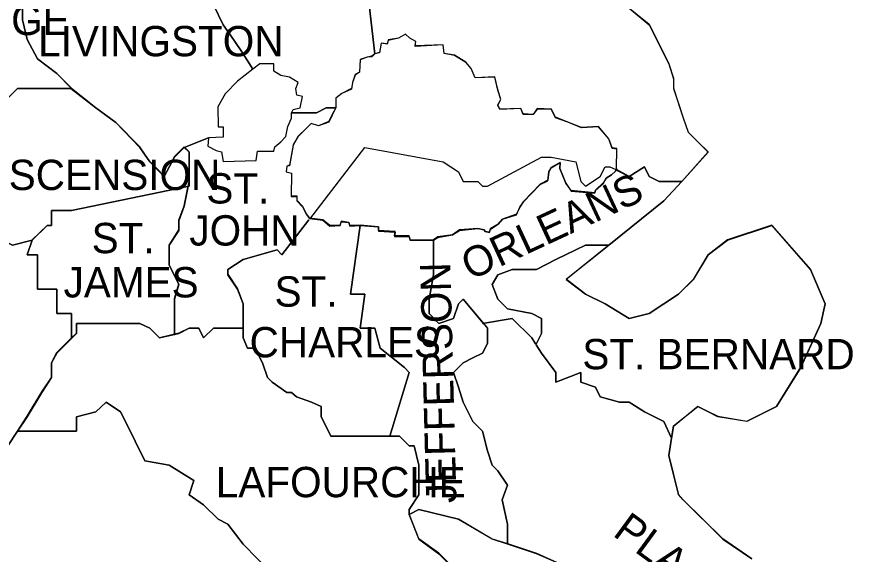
# Model space of a CAD drawing. Extents: x 0.19 to 2.82, y 0.04 to 1.79.
# Drawn here: x 2.4368 to 2.5672, y 1.4495 to 1.5325 of the extents above; entities that cross this region are included whole.
import ezdxf

# ---------------------------------------------------------------- set-up
doc = ezdxf.new("R2010")
doc.units = 0
for name, color, linetype in [('Dist02', 7, 'Continuous'), ('Dist61', 7, 'Continuous'), ('Dist62', 7, 'Continuous'), ('Standard Info', 7, 'Continuous')]:
    doc.layers.add(name, color=color, linetype=linetype)

msp = doc.modelspace()

# ---------------------------------------------------------------- linework, layer by layer
at = {"layer": 'Dist02'}
for points in [[(2.5294, 1.50908), (2.52924, 1.50867), (2.52865, 1.50808), (2.52782, 1.50758), (2.5274, 1.50692), (2.52615, 1.50575), (2.52607, 1.50533), (2.5224, 1.50567), (2.52157, 1.50683), (2.52065, 1.50908), (2.52074, 1.51), (2.51932, 1.50925), (2.51899, 1.50858), (2.51882, 1.50725), (2.51765, 1.50667), (2.51507, 1.504), (2.51449, 1.50308), (2.51399, 1.502), (2.51182, 1.50125), (2.51115, 1.5005), (2.5099, 1.49975), (2.50982, 1.49925), (2.50915, 1.49933), (2.50899, 1.49958), (2.50799, 1.49983), (2.50515, 1.49958), (2.50407, 1.49883), (2.50182, 1.4985), (2.50115, 1.49808)], [(2.53949, 1.50708), (2.53599, 1.50708), (2.53449, 1.50783), (2.53374, 1.50933), (2.5314, 1.50783), (2.5294, 1.50892)], [(2.53674, 1.50408), (2.53949, 1.50708)], [(2.52824, 1.49725), (2.53674, 1.50408)], [(2.4819, 1.50117), (2.47774, 1.49575), (2.47699, 1.4965), (2.47174, 1.495), (2.4694, 1.4935), (2.4694, 1.49275), (2.4709, 1.4905), (2.47174, 1.48817), (2.47174, 1.48442)], [(2.48982, 1.50033), (2.48824, 1.50025), (2.48807, 1.50075), (2.4869, 1.50092), (2.48674, 1.50033), (2.48515, 1.50025), (2.48407, 1.50117), (2.48199, 1.50142)], [(2.50115, 1.49808), (2.49757, 1.498), (2.4974, 1.49867), (2.49515, 1.49867), (2.49524, 1.49933), (2.49265, 1.4995), (2.49265, 1.50008), (2.48982, 1.50033)], [(2.5379, 1.4675), (2.53824, 1.46933), (2.54199, 1.47233), (2.54507, 1.47083), (2.54957, 1.47008), (2.55415, 1.47233), (2.5579, 1.47842), (2.56099, 1.48517), (2.56165, 1.48817), (2.5594, 1.4935), (2.5534, 1.50033), (2.54657, 1.49808), (2.54357, 1.49575), (2.54132, 1.492), (2.53899, 1.48967), (2.53449, 1.48667), (2.5314, 1.48592), (2.52765, 1.48817), (2.52465, 1.48967), (2.52165, 1.492), (2.52824, 1.49725)], [(2.47174, 1.48442), (2.46715, 1.48442), (2.46565, 1.48292), (2.4649, 1.48442), (2.4634, 1.48442), (2.46182, 1.48367), (2.45882, 1.48292), (2.45732, 1.48442), (2.45582, 1.48517), (2.45357, 1.48517), (2.44599, 1.48517), (2.44599, 1.48367), (2.44299, 1.48067), (2.44215, 1.47908), (2.44215, 1.47683), (2.44065, 1.47458), (2.4384, 1.47083), (2.4369, 1.4685)], [(2.4369, 1.4685), (2.4354, 1.46625), (2.43315, 1.4625), (2.43007, 1.461), (2.42932, 1.46025), (2.42707, 1.45875), (2.42482, 1.45942), (2.42332, 1.45875), (2.42182, 1.45725), (2.41874, 1.45417), (2.41724, 1.45192), (2.41799, 1.44967), (2.41799, 1.44817), (2.42032, 1.44508), (2.42182, 1.44358), (2.42182, 1.44208), (2.42099, 1.44133), (2.41949, 1.43983), (2.41799, 1.43825), (2.41574, 1.43492)], [(2.55032, 1.44883), (2.54582, 1.45192), (2.53974, 1.45792), (2.53899, 1.45875), (2.53749, 1.46475), (2.5379, 1.46742)], [(2.48407, 1.43608), (2.48532, 1.43525), (2.48907, 1.43075), (2.49207, 1.42617), (2.49665, 1.42092), (2.49815, 1.41942), (2.50115, 1.42092), (2.50424, 1.42317), (2.50799, 1.427), (2.50874, 1.42917), (2.50799, 1.43), (2.50799, 1.43375), (2.51024, 1.43825), (2.50874, 1.44283), (2.50499, 1.44658), (2.50199, 1.44967), (2.4989, 1.45192), (2.4974, 1.45567)], [(2.4974, 1.45567), (2.4989, 1.45642), (2.50499, 1.45492), (2.51024, 1.45192), (2.51257, 1.45117)], [(2.51257, 1.45117), (2.51707, 1.44967), (2.52232, 1.44733)]]:
    msp.add_lwpolyline(points, dxfattribs=at)
at = {"layer": 'Dist61'}
for points in [[(2.44524, 1.5215), (2.44299, 1.52375), (2.43999, 1.526), (2.4384, 1.529), (2.43765, 1.53208), (2.43765, 1.53508), (2.43765, 1.53892), (2.4384, 1.54117), (2.43999, 1.54417), (2.44215, 1.54642), (2.44374, 1.54867), (2.44524, 1.55017), (2.44674, 1.55325)], [(2.4634, 1.50633), (2.4634, 1.51167), (2.46265, 1.51242), (2.46115, 1.51092), (2.45957, 1.50783), (2.45882, 1.50867), (2.45732, 1.51017), (2.45582, 1.51242), (2.45207, 1.51617), (2.44899, 1.51842), (2.44515, 1.5215)], [(2.46115, 1.48367), (2.46115, 1.48667), (2.46115, 1.489), (2.46182, 1.49125), (2.46032, 1.49425), (2.46032, 1.49575), (2.46032, 1.49725), (2.46182, 1.49958), (2.46182, 1.50108), (2.46265, 1.50333), (2.46324, 1.50642)], [(2.44524, 1.48292), (2.44599, 1.48367), (2.44599, 1.48517), (2.45357, 1.48517), (2.45582, 1.48517), (2.45732, 1.48442), (2.45882, 1.48292), (2.46115, 1.4835)], [(2.4309, 1.46133), (2.43315, 1.4625), (2.4354, 1.46625), (2.4369, 1.4685), (2.4384, 1.47083), (2.44065, 1.47458), (2.44215, 1.47683), (2.44215, 1.47908), (2.44299, 1.48067), (2.44524, 1.48292)]]:
    msp.add_lwpolyline(points, dxfattribs=at)
at = {"layer": 'Dist62'}
for points in [[(2.44524, 1.5215), (2.44299, 1.52375), (2.43999, 1.526), (2.4384, 1.529), (2.43765, 1.53208), (2.43765, 1.53508), (2.43765, 1.53892), (2.4384, 1.54117), (2.43999, 1.54417), (2.44215, 1.54642), (2.44374, 1.54867), (2.44524, 1.55017), (2.44674, 1.55325)], [(2.52174, 1.551), (2.52232, 1.548), (2.5239, 1.54492), (2.52765, 1.53808), (2.53074, 1.53433), (2.53449, 1.53133), (2.53749, 1.52525), (2.53824, 1.523), (2.53824, 1.5215), (2.53974, 1.51692), (2.54049, 1.51467), (2.54199, 1.51317), (2.54357, 1.51167), (2.53949, 1.50708)], [(2.5294, 1.50908), (2.52949, 1.51217), (2.52874, 1.51225), (2.52824, 1.51367), (2.52665, 1.51558), (2.52399, 1.51542), (2.5219, 1.51625), (2.51999, 1.517), (2.5194, 1.51825), (2.51715, 1.51833), (2.51657, 1.51742), (2.51499, 1.5175), (2.51465, 1.51833), (2.5114, 1.51825), (2.51107, 1.51892), (2.51157, 1.51975), (2.51107, 1.52125), (2.51065, 1.52325), (2.50757, 1.52308), (2.50699, 1.5245), (2.50615, 1.5255), (2.5044, 1.52658), (2.50282, 1.52683), (2.50265, 1.52817), (2.49832, 1.528), (2.4984, 1.52867), (2.49749, 1.52917), (2.49682, 1.52983), (2.49574, 1.52917), (2.49415, 1.52892), (2.49399, 1.52833), (2.49307, 1.52842), (2.49282, 1.527), (2.49207, 1.52675)], [(2.49207, 1.52675), (2.49165, 1.52642), (2.4909, 1.52625), (2.48982, 1.52592), (2.48974, 1.52392), (2.48907, 1.52358), (2.48865, 1.52233), (2.48849, 1.52142), (2.48699, 1.52067), (2.48607, 1.51992), (2.48607, 1.51842)], [(2.4634, 1.50633), (2.4634, 1.51167), (2.46265, 1.51242), (2.46115, 1.51092), (2.45957, 1.50783), (2.45882, 1.50867), (2.45732, 1.51017), (2.45582, 1.51242), (2.45207, 1.51617), (2.44899, 1.51842), (2.44515, 1.5215)], [(2.48607, 1.51842), (2.48549, 1.51742), (2.48499, 1.51633), (2.4834, 1.51567), (2.48224, 1.516), (2.48149, 1.51525), (2.48024, 1.51408), (2.47949, 1.51275), (2.4789, 1.50958), (2.47849, 1.50942), (2.4784, 1.50858), (2.47924, 1.50833), (2.47915, 1.50483), (2.48007, 1.50483), (2.48007, 1.50417), (2.4809, 1.50325), (2.48149, 1.50208), (2.48199, 1.50142)], [(2.53949, 1.50708), (2.53599, 1.50708), (2.53449, 1.50783), (2.53374, 1.50933), (2.5314, 1.50783), (2.5294, 1.50892)], [(2.46115, 1.48367), (2.46115, 1.48667), (2.46115, 1.489), (2.46182, 1.49125), (2.46032, 1.49425), (2.46032, 1.49575), (2.46032, 1.49725), (2.46182, 1.49958), (2.46182, 1.50108), (2.46265, 1.50333), (2.46324, 1.50642)], [(2.4819, 1.50117), (2.47774, 1.49575), (2.47699, 1.4965), (2.47174, 1.495), (2.4694, 1.4935), (2.4694, 1.49275), (2.4709, 1.4905), (2.47174, 1.48817), (2.47174, 1.48442)], [(2.47174, 1.48442), (2.46715, 1.48442), (2.46565, 1.48292), (2.4649, 1.48442), (2.4634, 1.48442), (2.46182, 1.48367), (2.46115, 1.4835)]]:
    msp.add_lwpolyline(points, dxfattribs=at)
at = {"layer": 'Standard Info'}
for p, q in [((2.4664, 1.51383), (2.46265, 1.51233)), ((2.46265, 1.51233), (2.4664, 1.51383)), ((2.46265, 1.51233), (2.4664, 1.51383)), ((2.50882, 1.48517), (2.50874, 1.48517)), ((2.46115, 1.48358), (2.46115, 1.48342)), ((2.51699, 1.48183), (2.51707, 1.48208)), ((2.4369, 1.4685), (2.4369, 1.4685))]:
    msp.add_line(p, q, dxfattribs=at)
for points in [[(2.48307, 1.58192), (2.48149, 1.57283), (2.48457, 1.57058), (2.48532, 1.56833), (2.48607, 1.56458), (2.48757, 1.5615), (2.48832, 1.56), (2.48832, 1.55925), (2.48982, 1.5555), (2.48982, 1.54642), (2.49207, 1.52675)], [(2.47324, 1.52442), (2.47324, 1.52442), (2.47174, 1.52675), (2.47024, 1.529), (2.46865, 1.53125), (2.46715, 1.53433), (2.4679, 1.55625), (2.4679, 1.56075), (2.46715, 1.58117)], [(2.44674, 1.55317), (2.44524, 1.55017), (2.44374, 1.54867), (2.44215, 1.54642), (2.43999, 1.54408), (2.4384, 1.54108), (2.43765, 1.53883), (2.43765, 1.535), (2.43765, 1.532), (2.4384, 1.529), (2.43999, 1.526), (2.44299, 1.52375), (2.44524, 1.52142)], [(2.49207, 1.52675), (2.48982, 1.54642), (2.48982, 1.554)], [(2.52174, 1.551), (2.52232, 1.54792), (2.5239, 1.54492), (2.52765, 1.53808), (2.53074, 1.53433), (2.53449, 1.53125), (2.53749, 1.52525), (2.53824, 1.52292), (2.53824, 1.52142), (2.53974, 1.51692), (2.54049, 1.51467), (2.54199, 1.51317), (2.54357, 1.51158), (2.53949, 1.50708)], [(2.46765, 1.54842), (2.46715, 1.53433), (2.46865, 1.53125), (2.47024, 1.529), (2.47174, 1.52675), (2.47324, 1.52442)], [(2.46265, 1.51233), (2.46115, 1.51083), (2.45957, 1.50783), (2.45882, 1.50858), (2.45732, 1.51008), (2.45582, 1.51233), (2.45207, 1.51617), (2.44899, 1.51842), (2.44524, 1.52142), (2.44299, 1.52375), (2.43999, 1.526), (2.4384, 1.529), (2.43765, 1.532), (2.43765, 1.535), (2.43765, 1.53883), (2.4384, 1.54108), (2.43999, 1.54408), (2.44215, 1.54642), (2.44274, 1.54725)], [(2.5294, 1.509), (2.52949, 1.51208), (2.52874, 1.51217), (2.52824, 1.51367), (2.52665, 1.5155), (2.52399, 1.51533), (2.5219, 1.51625), (2.51999, 1.51692), (2.5194, 1.51817), (2.51715, 1.51825), (2.51657, 1.51742), (2.51499, 1.51742), (2.51465, 1.51833), (2.5114, 1.51817), (2.51107, 1.51883), (2.51157, 1.51975), (2.51107, 1.52117), (2.51065, 1.52317), (2.50757, 1.52308), (2.50699, 1.5245), (2.50615, 1.52542), (2.5044, 1.5265), (2.50282, 1.52683), (2.50265, 1.52817), (2.49832, 1.52792), (2.4984, 1.52867), (2.49749, 1.52917), (2.49682, 1.52983), (2.49574, 1.52917), (2.49415, 1.52883), (2.49399, 1.52825), (2.49307, 1.52842), (2.49282, 1.52692), (2.49207, 1.52675)], [(2.49207, 1.52675), (2.49165, 1.52633), (2.4909, 1.52625), (2.48982, 1.52583), (2.48974, 1.52392), (2.48907, 1.5235), (2.48865, 1.52233), (2.48849, 1.52133), (2.48699, 1.52067), (2.48607, 1.51992), (2.48607, 1.51842)], [(2.47324, 1.52442), (2.4709, 1.52258), (2.46899, 1.52058), (2.46782, 1.51858), (2.4679, 1.5155), (2.46865, 1.5155), (2.46865, 1.51392), (2.4664, 1.51383), (2.46265, 1.51233)], [(2.47924, 1.51767), (2.47949, 1.51817), (2.48057, 1.51842), (2.4809, 1.52017), (2.48007, 1.52042), (2.4799, 1.52142), (2.48024, 1.52233), (2.4789, 1.52317), (2.47757, 1.52342), (2.47649, 1.52408), (2.47649, 1.52525), (2.47432, 1.52525), (2.47324, 1.52442)], [(2.42857, 1.49725), (2.42857, 1.4995), (2.42857, 1.501), (2.43007, 1.50258), (2.43007, 1.50408), (2.4309, 1.50558), (2.43157, 1.51158), (2.4339, 1.51842), (2.4369, 1.52142), (2.44524, 1.52142)], [(2.44524, 1.52142), (2.4369, 1.52142), (2.43465, 1.51917)], [(2.44515, 1.52142), (2.44899, 1.51842), (2.45207, 1.51617), (2.45582, 1.51233), (2.45732, 1.51008), (2.45882, 1.50858), (2.45957, 1.50783), (2.46115, 1.51083), (2.46265, 1.51233), (2.4634, 1.51158), (2.4634, 1.50633)], [(2.48607, 1.51842), (2.48549, 1.51733), (2.48499, 1.51625), (2.4834, 1.51567), (2.48224, 1.516), (2.48149, 1.51525), (2.48024, 1.514), (2.47949, 1.51267), (2.4789, 1.5095), (2.47849, 1.50942), (2.4784, 1.50858), (2.47924, 1.50833), (2.47915, 1.50475), (2.48007, 1.50475), (2.48007, 1.50408), (2.4809, 1.50317), (2.48149, 1.502), (2.48199, 1.50133)], [(2.48607, 1.51842), (2.48457, 1.51842), (2.48307, 1.51767), (2.47924, 1.51767)], [(2.47924, 1.51767), (2.48307, 1.51767), (2.48457, 1.51842), (2.48607, 1.51842)], [(2.4664, 1.51383), (2.46632, 1.5125), (2.46757, 1.51183), (2.4684, 1.51167), (2.46865, 1.51017), (2.47374, 1.51033), (2.47399, 1.51175), (2.47649, 1.51175), (2.47665, 1.51242), (2.47757, 1.51317), (2.47832, 1.514), (2.47865, 1.51558), (2.47924, 1.51683), (2.47924, 1.51767)], [(2.46115, 1.48358), (2.46115, 1.48667), (2.46115, 1.48892), (2.46182, 1.49117), (2.46032, 1.49417), (2.46032, 1.49575), (2.46032, 1.49725), (2.46182, 1.4995), (2.46182, 1.501), (2.46265, 1.50325), (2.4634, 1.50708), (2.4634, 1.51158), (2.46265, 1.51233)], [(2.48207, 1.50125), (2.49057, 1.51233), (2.50265, 1.51008), (2.50499, 1.50858), (2.50574, 1.50708), (2.50799, 1.50708), (2.50874, 1.50633), (2.50949, 1.50633), (2.51782, 1.51083), (2.51932, 1.51083), (2.52315, 1.51008), (2.5239, 1.50708), (2.52465, 1.50633), (2.5269, 1.50783), (2.52765, 1.50933), (2.5284, 1.50933), (2.52932, 1.50892)], [(2.48207, 1.50125), (2.49057, 1.51233), (2.50265, 1.51008), (2.50499, 1.50858), (2.50574, 1.50708), (2.50799, 1.50708), (2.50874, 1.50633), (2.50949, 1.50633), (2.51782, 1.51083), (2.51932, 1.51083), (2.52315, 1.51008), (2.5239, 1.50708), (2.52465, 1.50633), (2.5269, 1.50783), (2.52765, 1.50933), (2.5284, 1.50933), (2.52932, 1.50892)], [(2.50115, 1.498), (2.50182, 1.49842), (2.50407, 1.49883), (2.50515, 1.4995), (2.50799, 1.49983), (2.50899, 1.49958), (2.50915, 1.49933), (2.50982, 1.49917), (2.5099, 1.49967), (2.51115, 1.5005), (2.51182, 1.50125), (2.51399, 1.50192), (2.51449, 1.50308), (2.51507, 1.50392), (2.51765, 1.50658), (2.51882, 1.50717), (2.51899, 1.50858), (2.51932, 1.50917), (2.52074, 1.51), (2.52065, 1.50908), (2.52157, 1.50683), (2.5224, 1.50558), (2.52607, 1.50525), (2.52615, 1.50575), (2.5274, 1.50683), (2.52782, 1.50758), (2.52865, 1.50808), (2.52924, 1.50867), (2.5294, 1.509)], [(2.5294, 1.50883), (2.5314, 1.50783), (2.53374, 1.50933), (2.53449, 1.50783), (2.53599, 1.50708), (2.53949, 1.50708)], [(2.53899, 1.50708), (2.53599, 1.50708), (2.53449, 1.50783), (2.53374, 1.50933), (2.5314, 1.50783), (2.5294, 1.50883)], [(2.4634, 1.50633), (2.44524, 1.50258), (2.44215, 1.50258), (2.44215, 1.50025), (2.44149, 1.50025), (2.43915, 1.498), (2.43615, 1.49725), (2.43465, 1.498), (2.4339, 1.498), (2.4324, 1.498), (2.4309, 1.498), (2.43007, 1.49875), (2.42857, 1.49725)], [(2.43915, 1.49808), (2.44149, 1.50025), (2.44215, 1.50025), (2.44215, 1.50258), (2.44524, 1.50258), (2.4634, 1.50633)], [(2.46324, 1.50633), (2.46265, 1.50325), (2.46182, 1.501), (2.46182, 1.4995), (2.46032, 1.49725), (2.46032, 1.49575), (2.46032, 1.49417), (2.46182, 1.49117), (2.46115, 1.48892), (2.46115, 1.48667), (2.46115, 1.48358)], [(2.53949, 1.50708), (2.53674, 1.50408)], [(2.53674, 1.50408), (2.52824, 1.49725)], [(2.4819, 1.50117), (2.47774, 1.49575), (2.47699, 1.4965), (2.47174, 1.495), (2.4694, 1.4935), (2.4694, 1.49267), (2.4709, 1.49042), (2.47174, 1.48817), (2.47174, 1.48442)], [(2.47174, 1.48442), (2.47174, 1.48817), (2.4709, 1.49042), (2.4694, 1.49267), (2.4694, 1.4935), (2.47174, 1.495), (2.47699, 1.4965), (2.47774, 1.49575), (2.4819, 1.50117)], [(2.48199, 1.50133), (2.48407, 1.50108), (2.48515, 1.50017), (2.48674, 1.50025), (2.4869, 1.50083), (2.48807, 1.50075), (2.48824, 1.50017), (2.48982, 1.50025)], [(2.48982, 1.50025), (2.48832, 1.48967), (2.49057, 1.48967), (2.48982, 1.48442), (2.49207, 1.48442), (2.4929, 1.48133), (2.49665, 1.47833), (2.4974, 1.47758), (2.4944, 1.46775)], [(2.4944, 1.46775), (2.4974, 1.47758), (2.49665, 1.47833), (2.4929, 1.48133), (2.49207, 1.48442), (2.48982, 1.48442), (2.49057, 1.48967), (2.48832, 1.48967), (2.48982, 1.50025)], [(2.48982, 1.50025), (2.49265, 1.50008), (2.49265, 1.49942), (2.49524, 1.49925), (2.49515, 1.49858), (2.4974, 1.49858), (2.49757, 1.498), (2.50115, 1.498)], [(2.52824, 1.49725), (2.52165, 1.49192), (2.52465, 1.48967), (2.52765, 1.48817), (2.5314, 1.48592), (2.53449, 1.48667), (2.53899, 1.48967), (2.54132, 1.49192), (2.54357, 1.49575), (2.54657, 1.498), (2.5534, 1.50025), (2.5594, 1.4935), (2.56165, 1.48817), (2.56099, 1.48517), (2.5579, 1.47833), (2.55415, 1.47233), (2.54957, 1.47), (2.54507, 1.47075), (2.54199, 1.47233), (2.53824, 1.46925), (2.5379, 1.46742)], [(2.42857, 1.49725), (2.43007, 1.49875), (2.4309, 1.498), (2.4324, 1.498), (2.4339, 1.498), (2.43465, 1.498), (2.43615, 1.49725), (2.43915, 1.498)], [(2.43915, 1.498), (2.4384, 1.49575), (2.43999, 1.49575), (2.43999, 1.49042), (2.44299, 1.49042), (2.44299, 1.48667), (2.44524, 1.48667), (2.44524, 1.48292)], [(2.44524, 1.48292), (2.44524, 1.48667), (2.44299, 1.48667), (2.44299, 1.49042), (2.43999, 1.49042), (2.43999, 1.49575), (2.4384, 1.49575), (2.43915, 1.498)], [(2.50115, 1.498), (2.50115, 1.49267), (2.50049, 1.48892), (2.50049, 1.48667), (2.50199, 1.48517), (2.50424, 1.48592), (2.50499, 1.48817), (2.50574, 1.48892), (2.50949, 1.48442), (2.50949, 1.48208), (2.50874, 1.48058), (2.50724, 1.47983), (2.50574, 1.47908), (2.50424, 1.47758), (2.50499, 1.47533), (2.50574, 1.473), (2.50724, 1.47), (2.50874, 1.4685), (2.50949, 1.4655), (2.51024, 1.46325), (2.51107, 1.46242), (2.51257, 1.46017), (2.51174, 1.45792), (2.51257, 1.45417), (2.51257, 1.45108)], [(2.5089, 1.48517), (2.50574, 1.48892), (2.50499, 1.48817), (2.50424, 1.48592), (2.50199, 1.48517), (2.50049, 1.48667), (2.50049, 1.48892), (2.50115, 1.49267), (2.50115, 1.498)], [(2.52824, 1.49725), (2.52615, 1.49725), (2.52465, 1.49725), (2.52315, 1.4965), (2.52007, 1.495), (2.51707, 1.4935), (2.51332, 1.4935), (2.51107, 1.49267), (2.51024, 1.49117), (2.51107, 1.48892), (2.51257, 1.48742), (2.51632, 1.48667), (2.51782, 1.48592), (2.51782, 1.48358), (2.51707, 1.48208)], [(2.51707, 1.48208), (2.51782, 1.48358), (2.51782, 1.48592), (2.51632, 1.48667), (2.51257, 1.48742), (2.51107, 1.48892), (2.51024, 1.49117), (2.51107, 1.49267), (2.51332, 1.4935), (2.51707, 1.4935), (2.52007, 1.495), (2.52315, 1.4965), (2.52465, 1.49725), (2.52615, 1.49725), (2.52824, 1.49725)], [(2.5169, 1.482), (2.51632, 1.48292), (2.51332, 1.48592), (2.50874, 1.48517)], [(2.50874, 1.48517), (2.51332, 1.48592), (2.51632, 1.48292), (2.5169, 1.482)], [(2.4369, 1.4685), (2.4384, 1.47075), (2.44065, 1.4745), (2.44215, 1.47683), (2.44215, 1.47908), (2.44299, 1.48058), (2.44599, 1.48358), (2.44599, 1.48517), (2.45357, 1.48517), (2.45582, 1.48517), (2.45732, 1.48442), (2.45882, 1.48292), (2.46182, 1.48358), (2.4634, 1.48442), (2.4649, 1.48442), (2.46565, 1.48292), (2.46715, 1.48442), (2.47174, 1.48442)], [(2.46115, 1.48342), (2.45882, 1.48292), (2.45732, 1.48442), (2.45582, 1.48517), (2.45357, 1.48517), (2.44599, 1.48517), (2.44599, 1.48358), (2.44524, 1.48283)], [(2.47174, 1.48442), (2.46715, 1.48442), (2.46565, 1.48292), (2.4649, 1.48442), (2.4634, 1.48442), (2.46182, 1.48358), (2.46115, 1.48342)], [(2.47174, 1.48442), (2.47174, 1.48292), (2.4724, 1.48133), (2.47324, 1.48133), (2.47399, 1.48058), (2.47474, 1.47908), (2.47549, 1.47683), (2.47624, 1.47608), (2.47849, 1.4745), (2.47924, 1.4745), (2.47999, 1.47383), (2.48232, 1.473), (2.48382, 1.47233), (2.48382, 1.47075), (2.48457, 1.46925), (2.48532, 1.46775), (2.4959, 1.46775), (2.4974, 1.46625), (2.49815, 1.46625), (2.4989, 1.46325), (2.4989, 1.46092), (2.4989, 1.45867), (2.4974, 1.45642), (2.4974, 1.45567)], [(2.4944, 1.46775), (2.48532, 1.46775), (2.48457, 1.46925), (2.48382, 1.47075), (2.48382, 1.47233), (2.48232, 1.473), (2.47999, 1.47383), (2.47924, 1.4745), (2.47849, 1.4745), (2.47624, 1.47608), (2.47549, 1.47683), (2.47474, 1.47908), (2.47399, 1.48058), (2.47324, 1.48133), (2.4724, 1.48133), (2.47174, 1.48292), (2.47174, 1.48442)], [(2.51257, 1.45108), (2.51257, 1.45417), (2.51174, 1.45792), (2.51257, 1.46017), (2.51107, 1.46242), (2.51024, 1.46325), (2.50949, 1.4655), (2.50874, 1.4685), (2.50724, 1.47), (2.50574, 1.473), (2.50499, 1.47533), (2.50424, 1.47758), (2.50574, 1.47908), (2.50724, 1.47983), (2.50874, 1.48058), (2.50949, 1.48208), (2.50949, 1.48442), (2.50882, 1.48517)], [(2.44524, 1.48283), (2.44299, 1.48058), (2.44215, 1.47908), (2.44215, 1.47683), (2.44065, 1.4745), (2.4384, 1.47075), (2.4369, 1.4685), (2.4354, 1.46625), (2.43315, 1.46242), (2.4309, 1.46133)], [(2.5379, 1.46742), (2.53674, 1.47), (2.53374, 1.4715), (2.5314, 1.473), (2.5299, 1.473), (2.5269, 1.47383), (2.52615, 1.47533), (2.5239, 1.47608), (2.5239, 1.47758), (2.52007, 1.47608), (2.52007, 1.47758), (2.51782, 1.48058), (2.51699, 1.48183)], [(2.51699, 1.48183), (2.51782, 1.48058), (2.52007, 1.47758), (2.52007, 1.47608), (2.5239, 1.47758), (2.5239, 1.47608), (2.52615, 1.47533), (2.5269, 1.47383), (2.5299, 1.473), (2.5314, 1.473), (2.53374, 1.4715), (2.53674, 1.47), (2.5379, 1.46742)], [(2.4369, 1.4685), (2.44599, 1.4685), (2.44599, 1.47075), (2.44899, 1.4715), (2.45057, 1.473), (2.45282, 1.4715), (2.45357, 1.47), (2.45507, 1.467), (2.45657, 1.46392), (2.46032, 1.46325), (2.46415, 1.46092), (2.4634, 1.45867), (2.46565, 1.45717), (2.4679, 1.45492), (2.4694, 1.45417), (2.47174, 1.45108), (2.47399, 1.44883), (2.47699, 1.44583), (2.47924, 1.44358), (2.48082, 1.43975), (2.48424, 1.43625)], [(2.48424, 1.43625), (2.48082, 1.43975), (2.47924, 1.44358), (2.47699, 1.44583), (2.47399, 1.44883), (2.47174, 1.45108), (2.4694, 1.45417), (2.4679, 1.45492), (2.46565, 1.45717), (2.4634, 1.45867), (2.46415, 1.46092), (2.46032, 1.46325), (2.45657, 1.46392), (2.45507, 1.467), (2.45357, 1.47), (2.45282, 1.4715), (2.45057, 1.473), (2.44899, 1.4715), (2.44599, 1.47075), (2.44599, 1.4685), (2.4369, 1.4685)], [(2.41574, 1.43492), (2.41799, 1.43825), (2.41949, 1.43975), (2.42099, 1.44125), (2.42182, 1.44208), (2.42182, 1.44358), (2.42032, 1.44508), (2.41799, 1.44808), (2.41799, 1.44958), (2.41724, 1.45183), (2.41874, 1.45417), (2.42182, 1.45717), (2.42332, 1.45867), (2.42482, 1.45942), (2.42707, 1.45867), (2.42932, 1.46017), (2.43007, 1.46092), (2.43315, 1.46242), (2.4354, 1.46625), (2.4369, 1.4685)], [(2.4974, 1.45567), (2.4974, 1.45642), (2.4989, 1.45867), (2.4989, 1.46092), (2.4989, 1.46325), (2.49815, 1.46625), (2.4974, 1.46625), (2.4959, 1.46775), (2.4944, 1.46775)], [(2.5379, 1.46742), (2.53749, 1.46475), (2.53899, 1.45867), (2.53974, 1.45792), (2.54582, 1.45183), (2.55032, 1.44883)], [(2.4974, 1.45567), (2.4989, 1.45183), (2.50199, 1.44958), (2.50499, 1.44658), (2.50874, 1.44275), (2.51024, 1.43825), (2.50799, 1.43367), (2.50799, 1.42992), (2.50874, 1.42917), (2.50799, 1.42692), (2.50424, 1.42308), (2.50115, 1.42083), (2.49815, 1.41933), (2.49665, 1.42083), (2.49207, 1.42617), (2.48907, 1.43067), (2.48532, 1.43525), (2.48407, 1.436)], [(2.51257, 1.45108), (2.51024, 1.45183), (2.50499, 1.45492), (2.4989, 1.45642), (2.4974, 1.45567)], [(2.52232, 1.44733), (2.51707, 1.44958), (2.51257, 1.45108)]]:
    msp.add_lwpolyline(points, dxfattribs=at)

# ---------------------------------------------------------------- texts
for s, p in [('ROUGE', (2.42202, 1.52967)), ('LIVINGSTON', (2.44009, 1.5264)), ('ASCENSION', (2.43137, 1.50575)), ('ST.', (2.46607, 1.50367)), ('JOHN', (2.46345, 1.49718)), ('ST.', (2.44835, 1.496)), ('JAMES', (2.44402, 1.48917)), ('ST.', (2.4766, 1.48775)), ('CHARLES', (2.47275, 1.47992)), ('ST. BERNARD', (2.52414, 1.47808)), ('LAFOURCHE', (2.46753, 1.45833))]:
    msp.add_text(s, height=0.004679, dxfattribs=at).set_placement(p)
for s, height, rotation, p in [('ORLEANS', 0.004678, 24.9246, (2.50686, 1.49175)), ('JEFFERSON', 0.004679, 91.4837, (2.50471, 1.45746)), ('PLAQUEMINES', 0.004679, 323.7253, (2.52868, 1.45249))]:
    msp.add_text(s, height=height, rotation=rotation, dxfattribs=at).set_placement(p)

doc.saveas('drawing.dxf')
